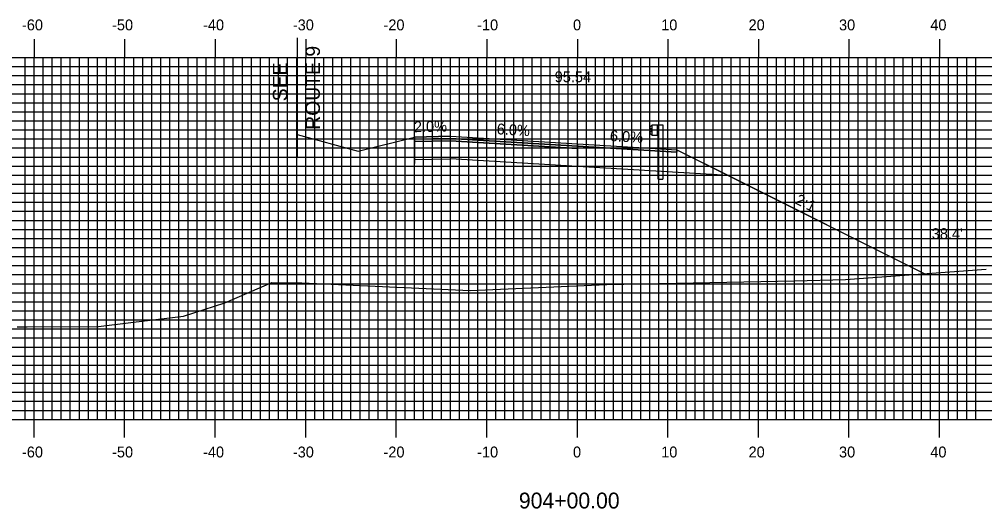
# Model space of a CAD drawing. Extents: x 857110 to 857453, y 364765 to 364985.
# Drawn here: x 857214.2 to 857320.8, y 364833.4 to 364887.5 of the extents above; entities that cross this region are included whole.
import ezdxf

# ---------------------------------------------------------------- set-up
doc = ezdxf.new("R2010")
doc.units = 0
for name, color, linetype in [('ANNOTATION', 7, 'Continuous'), ('D_Guardrail_Beam_Rt', 7, 'Continuous'), ('D_Roadway_Centerline', 7, 'Continuous'), ('D_Roadway_Centerline_Text', 7, 'Continuous'), ('D_Roadway_Edge_Shoulder', 7, 'Continuous'), ('D_Roadway_Edge_TW', 7, 'Continuous'), ('D_Roadway_Pavement', 7, 'Continuous'), ('D_Roadway_SlopeLines', 7, 'Continuous'), ('D_Roadway_SubGrade', 7, 'Continuous'), ('D_Text_Standard', 7, 'Continuous'), ('H_V ANNOTATION', 7, 'Continuous'), ('MAJOR', 7, 'Continuous'), ('MINOR', 7, 'Continuous'), ('S_Roadway_Centerline', 7, 'Continuous')]:
    doc.layers.add(name, color=color, linetype=linetype)

msp = doc.modelspace()

# ---------------------------------------------------------------- linework, layer by layer
at = {"layer": 'D_Guardrail_Beam_Rt'}
for p, q in [((857283.98, 364875.75), (857283.83, 364875.65)), ((857283.83, 364875.5), (857284.03, 364875.37)), ((857284.03, 364875.17), (857283.83, 364875.03)), ((857284.07, 364875.77), (857283.99, 364875.75)), ((857284.06, 364875.3), (857284.06, 364875.23)), ((857284.07, 364875.85), (857284.75, 364875.85)), ((857284.07, 364874.68), (857284.07, 364875.85)), ((857284.59, 364875.85), (857284.59, 364874.68)), ((857284.69, 364875.85), (857284.69, 364874.68)), ((857284.75, 364875.85), (857285.22, 364875.85)), ((857284.75, 364875.85), (857284.75, 364874.68)), ((857285.22, 364875.85), (857285.22, 364869.85)), ((857283.83, 364874.89), (857283.98, 364874.79)), ((857283.99, 364874.78), (857284.07, 364874.77)), ((857284.75, 364874.68), (857284.07, 364874.68)), ((857284.73, 364869.85), (857284.73, 364874.68)), ((857284.73, 364869.85), (857285.22, 364869.85))]:
    msp.add_line(p, q, dxfattribs=at)
for centre, major_axis, start_param, end_param in [((857283.88, 364875.57), (-0.0877, 0), 5.323254, 7.243116), ((857284, 364875.71), (-0.0417, 0), 4.907132, 5.323254), ((857283.98, 364875.3), (0.0789, 0), 0, 0.959931), ((857283.98, 364875.23), (0.0789, 0), 5.323254, 6.283185), ((857283.88, 364874.96), (-0.0877, 0), 5.323254, 7.243116), ((857284, 364874.82), (-0.0417, 0), 0.959931, 1.376053)]:
    msp.add_ellipse(centre, major_axis=major_axis, ratio=0.995501, start_param=start_param, end_param=end_param, dxfattribs=at)
at = {"layer": 'D_Roadway_Centerline'}
msp.add_lwpolyline([(857251.58, 364872.95), (857257.79, 364874.51), (857261.79, 364874.59), (857275.79, 364873.75), (857283.79, 364873.27), (857286.79, 364873.09), (857292.48, 364870.25), (857314.16, 364859.4)], dxfattribs=at)
at = {"layer": 'D_Roadway_Edge_Shoulder'}
for points in [[(857261.79, 364874.59), (857257.79, 364874.51), (857257.79, 364874.26), (857261.79, 364874.34)], [(857275.79, 364873.75), (857283.79, 364873.27), (857283.79, 364873.27), (857286.79, 364873.09), (857286.79, 364872.84), (857275.79, 364873.5)]]:
    msp.add_lwpolyline(points, close=True, dxfattribs=at)
at = {"layer": 'D_Roadway_Edge_TW'}
msp.add_lwpolyline([(857261.79, 364874.59), (857275.79, 364873.75), (857275.79, 364873.5), (857261.79, 364874.34)], close=True, dxfattribs=at)
at = {"layer": 'D_Roadway_Pavement'}
for points in [[(857261.79, 364874.34), (857257.79, 364874.26), (857257.79, 364874.01), (857261.79, 364874.09)], [(857261.79, 364874.34), (857275.79, 364873.5), (857275.79, 364873.25), (857261.79, 364874.09)]]:
    msp.add_lwpolyline(points, close=True, dxfattribs=at)
msp.add_lwpolyline([(857275.79, 364873.5), (857275.79, 364873.25)], dxfattribs=at)
msp.add_lwpolyline([(857275.79, 364873.5), (857275.79, 364873.25)], dxfattribs=at)
msp.add_lwpolyline([(857275.79, 364873.5), (857275.79, 364873.25)], dxfattribs=at)
at = {"layer": 'D_Roadway_SlopeLines'}
for points in [[(857244.83, 364874.78), (857251.58, 364872.95)], [(857286.79, 364873.09), (857314.16, 364859.4)]]:
    msp.add_lwpolyline(points, dxfattribs=at)
at = {"layer": 'D_Roadway_SubGrade'}
msp.add_line((857244.83, 364885.48), (857244.83, 364872.34), dxfattribs=at)
for points in [[(857261.79, 364874.09), (857257.79, 364874.01), (857257.79, 364874.26), (857257.79, 364874.51), (857257.79, 364872.01), (857261.79, 364872.09)], [(857261.79, 364874.09), (857275.79, 364873.25), (857275.79, 364871.25), (857261.79, 364872.09)], [(857275.79, 364873.25), (857275.79, 364873.5), (857286.79, 364872.84), (857286.79, 364873.09), (857292.48, 364870.25), (857275.79, 364871.25)]]:
    msp.add_lwpolyline(points, close=True, dxfattribs=at)
at = {"layer": 'MAJOR'}
for p, q in [((857215.79, 364885.31), (857215.79, 364883.3)), ((857225.79, 364885.31), (857225.79, 364883.3)), ((857235.79, 364885.31), (857235.79, 364883.3)), ((857245.79, 364885.31), (857245.79, 364883.3)), ((857255.79, 364885.31), (857255.79, 364883.3)), ((857265.79, 364885.31), (857265.79, 364883.3)), ((857275.79, 364885.31), (857275.79, 364883.3)), ((857285.79, 364885.31), (857285.79, 364883.3)), ((857295.79, 364885.31), (857295.79, 364883.3)), ((857305.79, 364885.31), (857305.79, 364883.3)), ((857315.79, 364885.31), (857315.79, 364883.3)), ((857135.79, 364883.3), (857415.79, 364883.3)), ((857135.79, 364883.3), (857415.79, 364883.3)), ((857215.79, 364843.3), (857215.79, 364883.3)), ((857225.79, 364843.3), (857225.79, 364883.3)), ((857235.79, 364843.3), (857235.79, 364883.3)), ((857245.79, 364843.3), (857245.79, 364883.3)), ((857255.79, 364843.3), (857255.79, 364883.3)), ((857265.79, 364843.3), (857265.79, 364883.3)), ((857275.79, 364843.3), (857275.79, 364883.3)), ((857285.79, 364843.3), (857285.79, 364883.3)), ((857295.79, 364843.3), (857295.79, 364883.3)), ((857305.79, 364843.3), (857305.79, 364883.3)), ((857315.79, 364843.3), (857315.79, 364883.3)), ((857135.79, 364878.3), (857415.79, 364878.3)), ((857135.79, 364873.3), (857415.79, 364873.3)), ((857135.79, 364868.3), (857415.79, 364868.3)), ((857135.79, 364863.3), (857415.79, 364863.3)), ((857135.79, 364858.3), (857415.79, 364858.3)), ((857135.79, 364853.3), (857415.79, 364853.3)), ((857135.79, 364848.3), (857415.79, 364848.3)), ((857135.79, 364843.3), (857415.79, 364843.3)), ((857135.79, 364843.3), (857415.79, 364843.3)), ((857215.79, 364841.3), (857215.79, 364843.3)), ((857225.79, 364841.3), (857225.79, 364843.3)), ((857235.79, 364841.3), (857235.79, 364843.3)), ((857245.79, 364841.3), (857245.79, 364843.3)), ((857255.79, 364841.3), (857255.79, 364843.3)), ((857265.79, 364841.3), (857265.79, 364843.3)), ((857275.79, 364841.3), (857275.79, 364843.3)), ((857285.79, 364841.3), (857285.79, 364843.3)), ((857295.79, 364841.3), (857295.79, 364843.3)), ((857305.79, 364841.3), (857305.79, 364843.3)), ((857315.79, 364841.3), (857315.79, 364843.3))]:
    msp.add_line(p, q, dxfattribs=at)
at = {"layer": 'MINOR'}
for p, q in [((857214.79, 364843.3), (857214.79, 364883.3)), ((857216.79, 364843.3), (857216.79, 364883.3)), ((857217.79, 364843.3), (857217.79, 364883.3)), ((857218.79, 364843.3), (857218.79, 364883.3)), ((857219.79, 364843.3), (857219.79, 364883.3)), ((857220.79, 364843.3), (857220.79, 364883.3)), ((857221.79, 364843.3), (857221.79, 364883.3)), ((857222.79, 364843.3), (857222.79, 364883.3)), ((857223.79, 364843.3), (857223.79, 364883.3)), ((857224.79, 364843.3), (857224.79, 364883.3)), ((857226.79, 364843.3), (857226.79, 364883.3)), ((857227.79, 364843.3), (857227.79, 364883.3)), ((857228.79, 364843.3), (857228.79, 364883.3)), ((857229.79, 364843.3), (857229.79, 364883.3)), ((857230.79, 364843.3), (857230.79, 364883.3)), ((857231.79, 364843.3), (857231.79, 364883.3)), ((857232.79, 364843.3), (857232.79, 364883.3)), ((857233.79, 364843.3), (857233.79, 364883.3)), ((857234.79, 364843.3), (857234.79, 364883.3)), ((857236.79, 364843.3), (857236.79, 364883.3)), ((857237.79, 364843.3), (857237.79, 364883.3)), ((857238.79, 364843.3), (857238.79, 364883.3)), ((857239.79, 364843.3), (857239.79, 364883.3)), ((857240.79, 364843.3), (857240.79, 364883.3)), ((857241.79, 364843.3), (857241.79, 364883.3)), ((857242.79, 364843.3), (857242.79, 364883.3)), ((857243.79, 364843.3), (857243.79, 364883.3)), ((857244.79, 364843.3), (857244.79, 364883.3)), ((857246.79, 364843.3), (857246.79, 364883.3)), ((857247.79, 364843.3), (857247.79, 364883.3)), ((857248.79, 364843.3), (857248.79, 364883.3)), ((857249.79, 364843.3), (857249.79, 364883.3)), ((857250.79, 364843.3), (857250.79, 364883.3)), ((857251.79, 364843.3), (857251.79, 364883.3)), ((857252.79, 364843.3), (857252.79, 364883.3)), ((857253.79, 364843.3), (857253.79, 364883.3)), ((857254.79, 364843.3), (857254.79, 364883.3)), ((857256.79, 364843.3), (857256.79, 364883.3)), ((857257.79, 364843.3), (857257.79, 364883.3)), ((857258.79, 364843.3), (857258.79, 364883.3)), ((857259.79, 364843.3), (857259.79, 364883.3)), ((857260.79, 364843.3), (857260.79, 364883.3)), ((857261.79, 364843.3), (857261.79, 364883.3)), ((857262.79, 364843.3), (857262.79, 364883.3)), ((857263.79, 364843.3), (857263.79, 364883.3)), ((857264.79, 364843.3), (857264.79, 364883.3)), ((857266.79, 364843.3), (857266.79, 364883.3)), ((857267.79, 364843.3), (857267.79, 364883.3)), ((857268.79, 364843.3), (857268.79, 364883.3)), ((857269.79, 364843.3), (857269.79, 364883.3)), ((857270.79, 364843.3), (857270.79, 364883.3)), ((857271.79, 364843.3), (857271.79, 364883.3)), ((857272.79, 364843.3), (857272.79, 364883.3)), ((857273.79, 364843.3), (857273.79, 364883.3)), ((857274.79, 364843.3), (857274.79, 364883.3)), ((857276.79, 364843.3), (857276.79, 364883.3)), ((857277.79, 364843.3), (857277.79, 364883.3)), ((857278.79, 364843.3), (857278.79, 364883.3)), ((857279.79, 364843.3), (857279.79, 364883.3)), ((857280.79, 364843.3), (857280.79, 364883.3)), ((857281.79, 364843.3), (857281.79, 364883.3)), ((857282.79, 364843.3), (857282.79, 364883.3)), ((857283.79, 364843.3), (857283.79, 364883.3)), ((857284.79, 364843.3), (857284.79, 364883.3)), ((857286.79, 364843.3), (857286.79, 364883.3)), ((857287.79, 364843.3), (857287.79, 364883.3)), ((857288.79, 364843.3), (857288.79, 364883.3)), ((857289.79, 364843.3), (857289.79, 364883.3)), ((857290.79, 364843.3), (857290.79, 364883.3)), ((857291.79, 364843.3), (857291.79, 364883.3)), ((857292.79, 364843.3), (857292.79, 364883.3)), ((857293.79, 364843.3), (857293.79, 364883.3)), ((857294.79, 364843.3), (857294.79, 364883.3)), ((857296.79, 364843.3), (857296.79, 364883.3)), ((857297.79, 364843.3), (857297.79, 364883.3)), ((857298.79, 364843.3), (857298.79, 364883.3)), ((857299.79, 364843.3), (857299.79, 364883.3)), ((857300.79, 364843.3), (857300.79, 364883.3)), ((857301.79, 364843.3), (857301.79, 364883.3)), ((857302.79, 364843.3), (857302.79, 364883.3)), ((857303.79, 364843.3), (857303.79, 364883.3)), ((857304.79, 364843.3), (857304.79, 364883.3)), ((857306.79, 364843.3), (857306.79, 364883.3)), ((857307.79, 364843.3), (857307.79, 364883.3)), ((857308.79, 364843.3), (857308.79, 364883.3)), ((857309.79, 364843.3), (857309.79, 364883.3)), ((857310.79, 364843.3), (857310.79, 364883.3)), ((857311.79, 364843.3), (857311.79, 364883.3)), ((857312.79, 364843.3), (857312.79, 364883.3)), ((857313.79, 364843.3), (857313.79, 364883.3)), ((857314.79, 364843.3), (857314.79, 364883.3)), ((857316.79, 364843.3), (857316.79, 364883.3)), ((857317.79, 364843.3), (857317.79, 364883.3)), ((857318.79, 364843.3), (857318.79, 364883.3)), ((857319.79, 364843.3), (857319.79, 364883.3)), ((857135.79, 364882.3), (857415.79, 364882.3)), ((857135.79, 364881.3), (857415.79, 364881.3)), ((857135.79, 364880.3), (857415.79, 364880.3)), ((857135.79, 364879.3), (857415.79, 364879.3)), ((857135.79, 364877.3), (857415.79, 364877.3)), ((857135.79, 364876.3), (857415.79, 364876.3)), ((857135.79, 364875.3), (857415.79, 364875.3)), ((857135.79, 364874.3), (857415.79, 364874.3)), ((857257.79, 364874.51), (857257.79, 364871.59)), ((857135.79, 364872.3), (857415.79, 364872.3)), ((857135.79, 364871.3), (857415.79, 364871.3)), ((857135.79, 364870.3), (857415.79, 364870.3)), ((857135.79, 364869.3), (857415.79, 364869.3)), ((857135.79, 364867.3), (857415.79, 364867.3)), ((857135.79, 364866.3), (857415.79, 364866.3)), ((857135.79, 364865.3), (857415.79, 364865.3)), ((857135.79, 364864.3), (857415.79, 364864.3)), ((857135.79, 364862.3), (857415.79, 364862.3)), ((857135.79, 364861.3), (857415.79, 364861.3)), ((857135.79, 364860.3), (857415.79, 364860.3)), ((857135.79, 364859.3), (857415.79, 364859.3)), ((857135.79, 364857.3), (857415.79, 364857.3)), ((857135.79, 364856.3), (857415.79, 364856.3)), ((857135.79, 364855.3), (857415.79, 364855.3)), ((857135.79, 364854.3), (857415.79, 364854.3)), ((857135.79, 364852.3), (857415.79, 364852.3)), ((857135.79, 364851.3), (857415.79, 364851.3)), ((857135.79, 364850.3), (857415.79, 364850.3)), ((857135.79, 364849.3), (857415.79, 364849.3)), ((857135.79, 364847.3), (857415.79, 364847.3)), ((857135.79, 364846.3), (857415.79, 364846.3)), ((857135.79, 364845.3), (857415.79, 364845.3)), ((857135.79, 364844.3), (857415.79, 364844.3))]:
    msp.add_line(p, q, dxfattribs=at)
at = {"layer": 'S_Roadway_Centerline'}
msp.add_lwpolyline([(857213.93, 364853.55), (857215.01, 364853.53), (857222.9, 364853.56), (857226.76, 364854.04), (857232.3, 364854.71), (857236.86, 364856.2), (857242.03, 364858.44), (857244.19, 364858.41), (857245.35, 364858.39), (857263.96, 364857.56), (857279.06, 364858.22), (857280.91, 364858.24), (857286.71, 364858.35), (857299.79, 364858.61), (857305.39, 364858.78), (857320.95, 364859.89)], dxfattribs=at)

# ---------------------------------------------------------------- texts
at = {"layer": 'ANNOTATION'}
for s, height, rotation, p in [('ROUTE 9', 1.6, 90, (857247.36, 364875.31)), ('SEE', 1.6, 90, (857243.76, 364878.46)), ('2.0%', 1.2, 1.1458, (857257.75, 364875.04)), ('6.0%', 1.2, 356.5664, (857266.86, 364874.82)), ('6.0%', 1.2, 356.5664, (857279.36, 364874.07)), ('2:1', 1.2, 333.4349, (857299.76, 364867.2))]:
    msp.add_text(s, height=height, rotation=rotation, dxfattribs=at).set_placement(p)
at = {"layer": 'D_Roadway_Centerline_Text'}
msp.add_text('95.54', height=1.2, dxfattribs=at).set_placement((857273.29, 364880.57))
at = {"layer": 'D_Text_Standard'}
msp.add_text("38.4'", height=1.2, dxfattribs=at).set_placement((857314.93, 364863.23))
at = {"layer": 'H_V ANNOTATION'}
for s, height, p in [('-60', 1.2, (857214.45, 364886.3)), ('-50', 1.2, (857224.4, 364886.3)), ('-40', 1.2, (857234.45, 364886.3)), ('-30', 1.2, (857244.37, 364886.3)), ('-20', 1.2, (857254.38, 364886.3)), ('-10', 1.2, (857264.72, 364886.3)), ('0', 1.2, (857275.31, 364886.3)), ('10', 1.2, (857285.05, 364886.3)), ('20', 1.2, (857294.7, 364886.3)), ('30', 1.2, (857304.69, 364886.3)), ('40', 1.2, (857314.77, 364886.3)), ('-60', 1.2, (857214.45, 364839.1)), ('-50', 1.2, (857224.4, 364839.1)), ('-40', 1.2, (857234.45, 364839.1)), ('-30', 1.2, (857244.37, 364839.1)), ('-20', 1.2, (857254.38, 364839.1)), ('-10', 1.2, (857264.72, 364839.1)), ('0', 1.2, (857275.31, 364839.1)), ('10', 1.2, (857285.05, 364839.1)), ('20', 1.2, (857294.7, 364839.1)), ('30', 1.2, (857304.69, 364839.1)), ('40', 1.2, (857314.77, 364839.1)), ('904+00.00', 1.75, (857269.33, 364833.46))]:
    msp.add_text(s, height=height, dxfattribs=at).set_placement(p)

doc.saveas('drawing.dxf')
